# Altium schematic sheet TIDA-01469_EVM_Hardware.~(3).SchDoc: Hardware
size 431 x 279 mm; Date: Not shown in title block; ApprovedBy: Not shown in title block; CheckedBy: Not shown in title block; Author: Not shown in title block; CompanyName: Not shown in title block; DrawnBy: Nathan Siegel; Engineer: Not shown in title block; Organization: Not shown in title block; Address1: Not shown in title block; Address2: Not shown in title block; Address3: Not shown in title block; Address4: Not shown in title block; DocumentNumber: 4; Revision: Use project parameter SCH_Rev; SheetNumber: 4; SheetTotal: 4; PageSetup: Record=PageOptions¦CenterHorizontal=True¦CenterVertical=True¦PrintScale=1.00¦XCorrection=1.00¦YCorrection=1.00¦PrintKind=0¦BorderSize=5000000¦LeftOffset=0¦BottomOffset=0¦Orientation=2¦PaperLength=1000¦PaperWidth=1000¦Scale=100¦PaperSource=15¦PrintQuality=600¦MediaType=1¦DitherType=10¦PaperKind=Letter¦PrintScaleMode=1
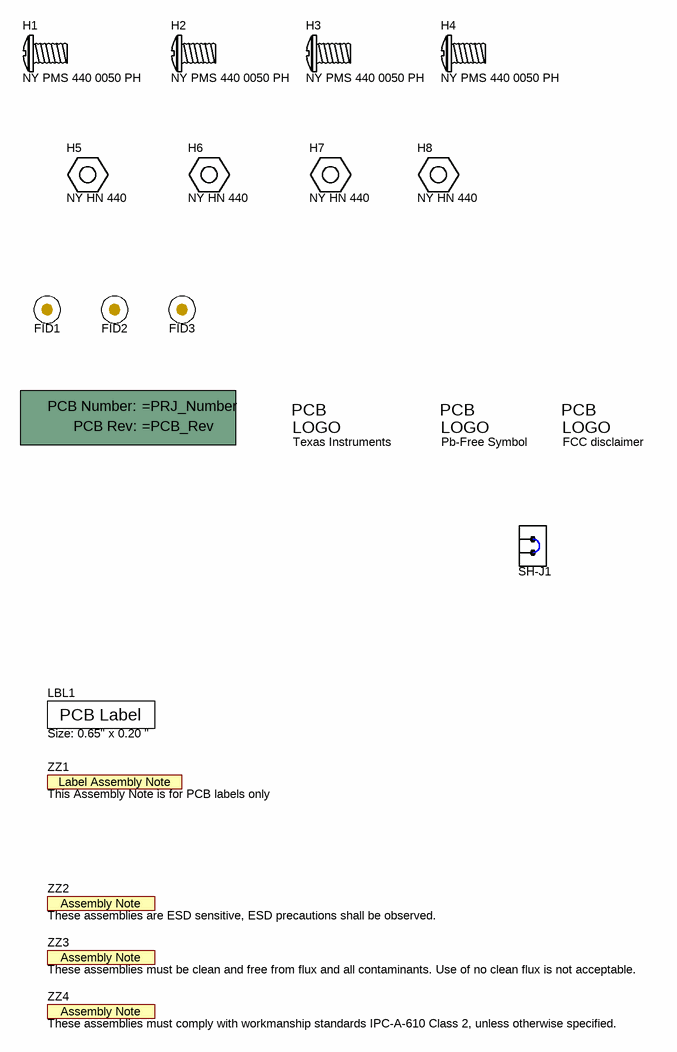
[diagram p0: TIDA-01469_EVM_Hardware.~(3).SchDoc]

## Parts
!PCB1  Printed Circuit Board  (value not drawn)  (mechanical)
FID1  Fiducial  [Fiducial10-20]  (value not drawn)
FID2  Fiducial  [Fiducial10-20]  (value not drawn)
FID3  Fiducial  [Fiducial10-20]  (value not drawn)
H1  NY PMS 440 0050 PH  (mechanical)
H2  NY PMS 440 0050 PH  (mechanical)
H3  NY PMS 440 0050 PH  (mechanical)
H4  NY PMS 440 0050 PH  (mechanical)
H5  NY HN 440  (mechanical)
H6  NY HN 440  (mechanical)
H7  NY HN 440  (mechanical)
H8  NY HN 440  (mechanical)
LBL1  Size: 0.65" x 0.20 "  [Label_650x200]
Logo1  Texas Instruments  [TI_Stacked_Overlay_Small]  (no BOM)
Logo2  Pb-Free Symbol  [Pb-Free_Overlay_Small]  (no BOM)
Logo3  FCC disclaimer  [FCC_disclaimer]  (no BOM)
SH-J1  969102-0000-DA  [SNT-100-BK-G]  (value not drawn)
ZZ1  This Assembly Note is for PCB labels only  [AssemblyNoteLabel]  (no BOM)
ZZ2  These assemblies are ESD sensitive, ESD precautions shall be observed.  [AssemblyNote]  (no BOM)
ZZ3  These assemblies must be clean and free from flux and all contaminants. Use of no clean flux is not acceptable.  [AssemblyNote]  (no BOM)
ZZ4  These assemblies must comply with workmanship standards IPC-A-610 Class 2, unless otherwise specified.  [AssemblyNote]  (no BOM)

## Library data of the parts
!PCB1 = PCB: Manufacturer: Any; SymbolCreator: a0412235
FID1-FID3 = Fiducial: Fiducial mark.  There is nothing to buy or mount.; SymbolCreator: codlsc
H1-H4 = NY PMS 440 0050 PH: MACHINE SCREW PAN PHILLIPS 4-40; Manufacturer: B&F Fastener Supply; SymbolCreator: a0412235; Green_Lifecycle: Not Set; Green_REACh: Incomplete
H5-H8 = NY HN 440: Nut, Hex, 4-40, Nylon; Manufacturer: B&F Fastener Supply; SymbolCreator: a0412235; Green_Lifecycle: Not Set; Green_REACh: Incomplete
LBL1 = THT-14-423-10: Thermal Transfer Printable Labels, 0.650" W x 0.200" H - 10,000 per roll; Manufacturer: Brady; SymbolCreator: a0412235; CompType: Label
Logo1 = TI_Logo: Texas Instrument Corporate Signature; SymbolCreator: codlsc
Logo2 = Pb-Free: SymbolCreator: a0412235
Logo3 = FCC_disclaimer: SymbolCreator: codlsc
SH-J1 = 969102-0000-DA: Shunt, 100mil, Gold plated, Black; Manufacturer: 3M; Alternate Manufacturer: Samtec; Value: 1x2; Note: You can "mate" this to a header by matching the designator.  i.e. use SH-J3 for header J3; Green_Lifecycle: Active; Green_REACh: Passed
ZZ1 = AssemblyNoteLabel: SymbolCreator: a0412235
ZZ2-ZZ4 = AssemblyNote: SymbolCreator: codlsc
